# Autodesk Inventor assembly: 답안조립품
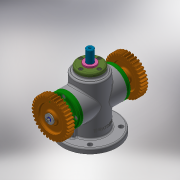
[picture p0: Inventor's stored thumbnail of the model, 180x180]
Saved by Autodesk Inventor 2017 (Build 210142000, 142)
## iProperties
Part Number: 답안조립품
Material: 일반
Document SubType Name: Assembly
Designer: 00-00
Author: 00-00
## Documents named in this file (17)
- C:\Users\00-00\Desktop\600606V1016\답안조립품.iam
- C:\Users\00-00\Desktop\600606V1016\본체.ipt
- C:\Users\00-00\Desktop\600606V1016\편심축.ipt
- C:\Users\00-00\Desktop\600606V1016\Ű 4x4x12.ipt
- C:\Users\00-00\Desktop\600606V1016\베어링 6203.ipt
- C:\Users\00-00\Desktop\600606V1016\커버 A.ipt
- C:\Users\00-00\Desktop\600606V1016\오일 실 17 30 8.ipt
- C:\Users\00-00\Desktop\600606V1016\스퍼기어.ipt
- C:\Users\00-00\Desktop\600606V1016\평와셔.ipt
- C:\Users\00-00\Desktop\600606V1016\스프링와셔.ipt
- C:\Users\00-00\Desktop\600606V1016\볼트 M4.ipt
- C:\Users\00-00\Desktop\600606V1016\슬라이더.ipt
- C:\Users\00-00\Desktop\600606V1016\가변스프링.ipt
- C:\Users\00-00\Desktop\600606V1016\스프링조립용 와셔.ipt
- C:\Users\00-00\Desktop\600606V1016\멈춤링.ipt
- C:\Users\00-00\Desktop\600606V1016\부시.ipt
- C:\Users\00-00\Desktop\600606V1016\커버 B.ipt
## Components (3 placed, 2 different names)
1. Ű 4x4x12:1 — 각도:1, 각도:2
2. Ű 4x4x12:2 — 각도:3, 각도:4
3. 가변스프링:1
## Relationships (4: Angle 4)
- 각도:1 [Angle]: Ű 4x4x12:1
- 각도:2 [Angle]: Ű 4x4x12:1
- 각도:3 [Angle]: Ű 4x4x12:2
- 각도:4 [Angle]: Ű 4x4x12:2
